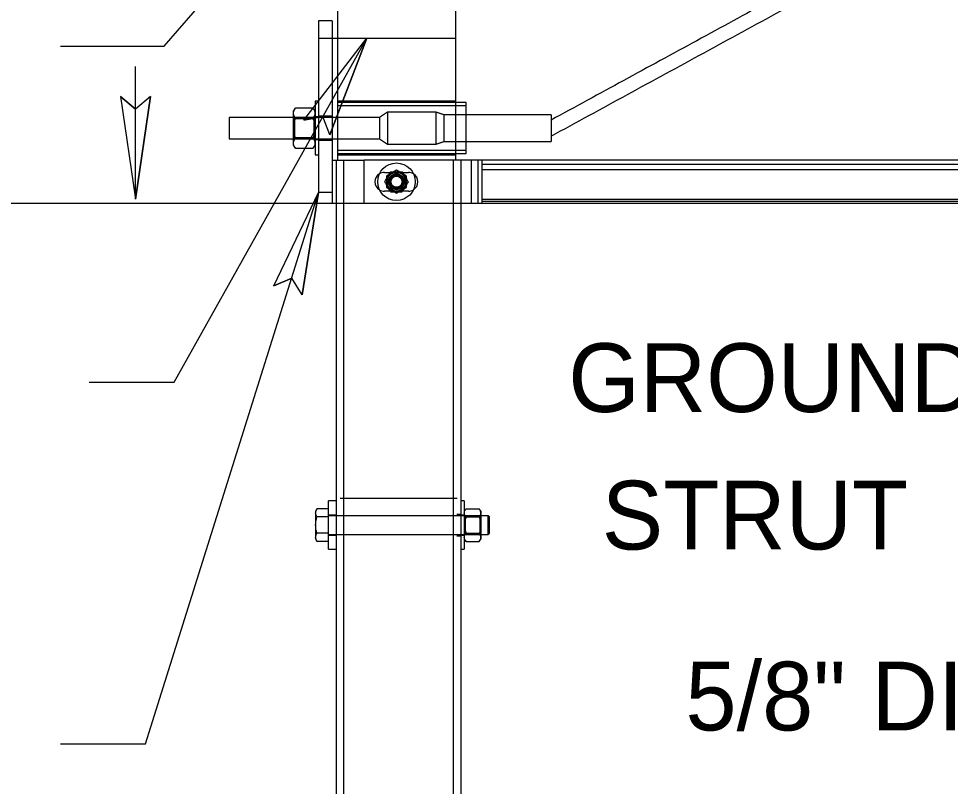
# Model space of a CAD drawing. Extents: x 12.2 to 54.5, y -7.8 to 16.1.
# Drawn here: x 13.367 to 14.18, y 14.128 to 14.798 of the extents above; entities that cross this region are included whole.
import ezdxf

# ---------------------------------------------------------------- set-up
doc = ezdxf.new("R2010")
doc.units = 0
for name, color, linetype in [('BORD-LINE', 7, 'Continuous'), ('DETL-DIMS', 7, 'Continuous'), ('DETL-NOTE', 7, 'Continuous')]:
    doc.layers.add(name, color=color, linetype=linetype)

msp = doc.modelspace()

# ---------------------------------------------------------------- linework, layer by layer
at = {"layer": 'BORD-LINE'}
for p, q in [((13.64499, 15.2566), (13.64499, 14.67435)), ((13.74802, 15.2566), (13.74802, 14.67435)), ((13.6286, 14.7961), (13.6286, 14.64625)), ((13.64031, 14.7961), (13.6286, 14.7961)), ((13.64031, 14.7961), (13.64031, 14.64625)), ((13.6286, 14.7811), (13.74802, 14.7811)), ((13.62561, 14.72586), (13.62561, 14.67903)), ((13.60665, 14.71562), (13.60665, 14.71766)), ((13.60852, 14.72002), (13.62373, 14.72002)), ((13.75738, 14.70244), (13.75738, 14.72469)), ((13.55046, 14.71181), (13.55046, 14.70244)), ((13.60665, 14.70244), (13.60665, 14.71562)), ((13.60667, 14.71181), (13.60667, 14.69308)), ((13.60749, 14.71064), (13.60749, 14.70244)), ((13.60852, 14.71123), (13.62373, 14.71123)), ((13.62479, 14.69425), (13.62479, 14.71064)), ((13.68158, 14.71181), (13.68158, 14.70244)), ((13.6886, 14.71649), (13.6886, 14.70244)), ((13.73777, 14.71415), (13.73777, 14.70244)), ((13.83143, 14.71415), (13.83143, 14.70244)), ((13.55046, 14.70244), (13.55046, 14.69308)), ((13.60665, 14.68926), (13.60665, 14.70244)), ((13.60749, 14.70244), (13.60749, 14.69425)), ((13.68158, 14.70244), (13.68158, 14.69308)), ((13.6886, 14.70244), (13.6886, 14.6884)), ((13.73777, 14.70244), (13.73777, 14.69074)), ((13.75738, 14.6802), (13.75738, 14.70244)), ((13.83143, 14.70244), (13.83143, 14.69074)), ((13.60852, 14.69366), (13.62373, 14.69366)), ((13.60665, 14.68723), (13.60665, 14.68926)), ((13.60852, 14.68487), (13.62373, 14.68487)), ((13.64031, 14.67435), (13.64734, 14.67435)), ((13.64382, 14.67435), (13.64382, 13.32571)), ((13.64734, 14.67435), (13.66841, 14.67435)), ((13.65041, 14.67435), (13.65041, 13.32571)), ((13.66841, 14.63689), (13.66841, 14.67435)), ((13.76206, 14.67435), (13.66841, 14.67435)), ((13.74612, 14.67435), (13.74612, 13.32571)), ((13.7527, 14.67435), (13.7527, 13.32571)), ((13.76206, 14.63689), (13.76206, 14.67435)), ((13.77143, 14.67435), (13.76206, 14.67435)), ((13.76792, 14.63689), (13.76792, 14.67435)), ((13.77143, 14.63689), (13.77143, 14.67435)), ((15.02641, 14.67435), (13.77143, 14.67435)), ((15.02641, 14.6706), (13.77143, 14.6706)), ((13.68597, 14.66381), (13.70704, 14.66381)), ((13.6965, 14.66565), (13.68781, 14.66063)), ((13.68781, 14.66063), (13.68781, 14.6506)), ((13.7052, 14.66063), (13.6965, 14.66565)), ((13.7052, 14.6506), (13.7052, 14.66063)), ((15.02641, 14.66591), (13.77143, 14.66591)), ((13.64031, 14.64625), (13.6286, 14.64625)), ((13.64031, 14.64625), (13.64031, 14.63689)), ((13.70704, 14.64742), (13.68597, 14.64742)), ((13.68781, 14.6506), (13.6965, 14.64558)), ((13.6965, 14.64558), (13.7052, 14.6506)), ((12.39652, 14.63689), (18.94051, 14.63689)), ((15.02641, 14.64026), (13.77143, 14.64026)), ((15.02641, 14.63838), (13.77143, 14.63838)), ((13.63731, 14.33485), (13.63731, 14.37699)), ((13.6473, 14.37939), (13.74936, 14.37942)), ((13.7557, 14.37699), (13.7557, 14.33485)), ((13.626, 14.36821), (13.626, 14.36656)), ((13.63731, 14.37011), (13.6271, 14.37011)), ((13.75733, 14.37011), (13.76859, 14.37011)), ((13.77023, 14.36821), (13.77023, 14.36656)), ((13.626, 14.36656), (13.626, 14.35592)), ((13.63731, 14.36301), (13.6271, 14.36301)), ((13.75571, 14.36411), (13.75571, 14.35592)), ((13.75643, 14.36309), (13.75643, 14.34875)), ((13.75733, 14.36301), (13.76859, 14.36301)), ((13.76951, 14.35592), (13.76951, 14.36309)), ((13.77023, 14.36656), (13.77023, 14.35592)), ((13.77656, 14.34772), (13.77656, 14.36411)), ((13.7778, 14.34896), (13.7778, 14.36287)), ((13.626, 14.35592), (13.626, 14.34528)), ((13.75571, 14.35592), (13.75571, 14.34772)), ((13.76951, 14.34875), (13.76951, 14.35592)), ((13.77023, 14.35592), (13.77023, 14.34528)), ((13.626, 14.34528), (13.626, 14.34363)), ((13.63731, 14.34882), (13.6271, 14.34882)), ((13.75733, 14.34882), (13.76859, 14.34882)), ((13.77023, 14.34528), (13.77023, 14.34363)), ((13.63731, 14.34173), (13.6271, 14.34173)), ((13.75733, 14.34173), (13.76859, 14.34173))]:
    msp.add_line(p, q, dxfattribs=at)
for centre, radius in [((13.69651, 14.65562), 0.01639), ((13.6965, 14.65562), 0.0082), ((13.69651, 14.65562), 0.00702), ((13.6965, 14.65562), 0.00614), ((13.69651, 14.65562), 0.00585), ((13.6965, 14.65562), 0.00498), ((13.69651, 14.65562), 0.00484)]:
    msp.add_circle(centre, radius, dxfattribs=at)
for centre, radius, start, end in [((13.68597, 14.65562), 0.00819, 121.58838, 238.41162), ((13.68597, 14.65561), 0.0082, 90.00567, 121.57898), ((13.69651, 14.65562), 0.00869, 120.00541, 179.99474), ((13.69651, 14.65562), 0.00878, 90.00226, 150.00113), ((13.6965, 14.65562), 0.00869, 59.99841, 120.00159), ((13.69651, 14.65562), 0.00878, 29.99887, 90.00233), ((13.69651, 14.65562), 0.00869, 359.99027, 60.00957), ((13.70704, 14.65562), 0.00819, 58.40904, 90.00139), ((13.70704, 14.65562), 0.00819, 301.57954, 58.42046), ((13.6965, 14.65562), 0.00878, 149.99162, 210.00838), ((13.69651, 14.65562), 0.00869, 180.00526, 239.99459), ((13.69651, 14.65562), 0.00869, 299.99043, 0.00973), ((13.69651, 14.65562), 0.00878, 329.99162, 30.00838), ((13.68597, 14.65562), 0.0082, 238.41635, 269.999), ((13.69651, 14.65562), 0.00878, 209.99887, 269.99774), ((13.6965, 14.65562), 0.00869, 239.99841, 300.00159), ((13.69651, 14.65562), 0.00878, 269.99767, 330.00113), ((13.70704, 14.65561), 0.00819, 269.99609, 301.59348)]:
    msp.add_arc(centre, radius, start, end, dxfattribs=at)
for points, degree in [([(13.83143, 14.69542), (14.36586, 14.98687)], 1), ([(14.3398, 14.98655), (13.83143, 14.70947)], 1), ([(13.6286, 14.72586), (13.62561, 14.72586)], 1), ([(13.74802, 14.72586), (13.64499, 14.72586)], 1), ([(13.60852, 14.72002), (13.60665, 14.71766)], 1), ([(13.60665, 14.71562), (13.60672, 14.7162), (13.60685, 14.71742), (13.60766, 14.71887), (13.60828, 14.7197), (13.60852, 14.72002)], 3), ([(13.62561, 14.71766), (13.62373, 14.72002)], 1), ([(13.62561, 14.71562), (13.62554, 14.7162), (13.62541, 14.71742), (13.6246, 14.71887), (13.62398, 14.7197), (13.62373, 14.72002)], 3), ([(13.74802, 14.72469), (13.64499, 14.72469)], 1), ([(13.75738, 14.7218), (13.64499, 14.7218)], 1), ([(13.75738, 14.72469), (13.74802, 14.72469)], 1), ([(13.60665, 14.71181), (13.55046, 14.71181)], 1), ([(13.60852, 14.71123), (13.60808, 14.71183), (13.60723, 14.71299), (13.60669, 14.71457), (13.60666, 14.71544), (13.60665, 14.71562)], 3), ([(13.64031, 14.71181), (13.60665, 14.71181)], 1), ([(13.60667, 14.71181), (13.60665, 14.71181)], 1), ([(13.60665, 14.70244), (13.60666, 14.70283), (13.60669, 14.7044), (13.60713, 14.70718), (13.60792, 14.70969), (13.60845, 14.71103), (13.60852, 14.71123)], 3), ([(13.60749, 14.71064), (13.60667, 14.71181)], 1), ([(13.62479, 14.71064), (13.60749, 14.71064)], 1), ([(13.62373, 14.71123), (13.62417, 14.71183), (13.62503, 14.71299), (13.62557, 14.71457), (13.6256, 14.71544), (13.62561, 14.71562)], 3), ([(13.62561, 14.70244), (13.6256, 14.70283), (13.62557, 14.7044), (13.62513, 14.70718), (13.62434, 14.70969), (13.62381, 14.71103), (13.62373, 14.71123)], 3), ([(13.62561, 14.71181), (13.62479, 14.71064)], 1), ([(13.6286, 14.71239), (13.62561, 14.71239)], 1), ([(13.64031, 14.71298), (13.6286, 14.71298)], 1), ([(13.64499, 14.71181), (13.64031, 14.71181)], 1), ([(13.68158, 14.71181), (13.64499, 14.71181)], 1), ([(13.6886, 14.71649), (13.68746, 14.71566), (13.68519, 14.71399), (13.68278, 14.71254), (13.68158, 14.71181)], 3), ([(13.73075, 14.71649), (13.6886, 14.71649)], 1), ([(13.73075, 14.71649), (13.73075, 14.7164), (13.73075, 14.71605), (13.73075, 14.71526), (13.73075, 14.71398), (13.73075, 14.71225), (13.73075, 14.71015), (13.73075, 14.70775), (13.73075, 14.70515), (13.73075, 14.70336), (13.73075, 14.70244)], 3), ([(13.73777, 14.71415), (13.73075, 14.71649)], 1), ([(13.75738, 14.71415), (13.73777, 14.71415)], 1), ([(13.83143, 14.71415), (13.75738, 14.71415)], 1), ([(13.83143, 14.70947), (13.83142, 14.70947)], 1), ([(13.60852, 14.69366), (13.60825, 14.6944), (13.60759, 14.69617), (13.60683, 14.6991), (13.60671, 14.70132), (13.60665, 14.70244)], 3), ([(13.62373, 14.69366), (13.62401, 14.6944), (13.62467, 14.69617), (13.62543, 14.6991), (13.62555, 14.70132), (13.62561, 14.70244)], 3), ([(13.73075, 14.70244), (13.73075, 14.70153), (13.73075, 14.69974), (13.73075, 14.69714), (13.73075, 14.69474), (13.73075, 14.69264), (13.73075, 14.69091), (13.73075, 14.68963), (13.73075, 14.68884), (13.73075, 14.68849), (13.73075, 14.6884)], 3), ([(13.55046, 14.69308), (13.60665, 14.69308)], 1), ([(13.60665, 14.68926), (13.60672, 14.68984), (13.60685, 14.69106), (13.60766, 14.69251), (13.60828, 14.69334), (13.60852, 14.69366)], 3), ([(13.60665, 14.69308), (13.64031, 14.69308)], 1), ([(13.60665, 14.69308), (13.60667, 14.69308)], 1), ([(13.60667, 14.69308), (13.60749, 14.69425)], 1), ([(13.60749, 14.69425), (13.62479, 14.69425)], 1), ([(13.62561, 14.68926), (13.62554, 14.68984), (13.62541, 14.69106), (13.6246, 14.69251), (13.62398, 14.69334), (13.62373, 14.69366)], 3), ([(13.62479, 14.69425), (13.62561, 14.69308)], 1), ([(13.64031, 14.69308), (13.64499, 14.69308)], 1), ([(13.64499, 14.69308), (13.68158, 14.69308)], 1), ([(13.68158, 14.69308), (13.68278, 14.69235), (13.68519, 14.6909), (13.68746, 14.68923), (13.6886, 14.6884)], 3), ([(13.60852, 14.68487), (13.60808, 14.68547), (13.60723, 14.68663), (13.60669, 14.68821), (13.60666, 14.68908), (13.60665, 14.68926)], 3), ([(13.60665, 14.68723), (13.60852, 14.68487)], 1), ([(13.62373, 14.68487), (13.62417, 14.68547), (13.62503, 14.68663), (13.62557, 14.68821), (13.6256, 14.68908), (13.62561, 14.68926)], 3), ([(13.62373, 14.68487), (13.62561, 14.68723)], 1), ([(13.62561, 14.6925), (13.6286, 14.6925)], 1), ([(13.6286, 14.69191), (13.64031, 14.69191)], 1), ([(13.6886, 14.6884), (13.73075, 14.6884)], 1), ([(13.73075, 14.6884), (13.73777, 14.69074)], 1), ([(13.73777, 14.69074), (13.75738, 14.69074)], 1), ([(13.75738, 14.69074), (13.83143, 14.69074)], 1), ([(13.62561, 14.67903), (13.6286, 14.67903)], 1), ([(13.64499, 14.68309), (13.75738, 14.68309)], 1), ([(13.64499, 14.6802), (13.74802, 14.6802)], 1), ([(13.64499, 14.67903), (13.74802, 14.67903)], 1), ([(13.74802, 14.6802), (13.75738, 14.6802)], 1), ([(13.6889, 14.66001), (13.68925, 14.66062), (13.68996, 14.66184), (13.6908, 14.66331), (13.69129, 14.66416), (13.69143, 14.6644)], 3), ([(13.69143, 14.6644), (13.69187, 14.6644), (13.69291, 14.6644), (13.6946, 14.6644), (13.69586, 14.6644), (13.6965, 14.6644)], 3), ([(13.6965, 14.6644), (13.69662, 14.6644), (13.69738, 14.6644), (13.69877, 14.6644), (13.70034, 14.6644), (13.70128, 14.6644), (13.70158, 14.6644)], 3), ([(13.70158, 14.6644), (13.70198, 14.66371), (13.70281, 14.66227), (13.70366, 14.6608), (13.7041, 14.66003), (13.70411, 14.66001)], 3), ([(13.68636, 14.65562), (13.68676, 14.65631), (13.6876, 14.65775), (13.68843, 14.65922), (13.68889, 14.65999), (13.6889, 14.66001)], 3), ([(13.6889, 14.65122), (13.68854, 14.65184), (13.68784, 14.65306), (13.68699, 14.65452), (13.6865, 14.65538), (13.68636, 14.65562)], 3), ([(13.70411, 14.66001), (13.70447, 14.6594), (13.70517, 14.65817), (13.70602, 14.65671), (13.70651, 14.65586), (13.70665, 14.65562)], 3), ([(13.70665, 14.65562), (13.70625, 14.65492), (13.70542, 14.65348), (13.70457, 14.65202), (13.70412, 14.65124), (13.70411, 14.65122)], 3), ([(13.69143, 14.64683), (13.69103, 14.64752), (13.6902, 14.64897), (13.68935, 14.65043), (13.68891, 14.6512), (13.6889, 14.65122)], 3), ([(13.69143, 14.64683), (13.69187, 14.64683), (13.69291, 14.64683), (13.6946, 14.64683), (13.69586, 14.64683), (13.6965, 14.64683)], 3), ([(13.6965, 14.64683), (13.69662, 14.64683), (13.69738, 14.64683), (13.69877, 14.64683), (13.70034, 14.64683), (13.70128, 14.64683), (13.70158, 14.64683)], 3), ([(13.70411, 14.65122), (13.70376, 14.65061), (13.70305, 14.64939), (13.70221, 14.64793), (13.70172, 14.64707), (13.70158, 14.64683)], 3), ([(13.64378, 14.37699), (13.63731, 14.37699)], 1), ([(13.7557, 14.37699), (13.7527, 14.37699)], 1), ([(13.626, 14.36656), (13.626, 14.36664), (13.62601, 14.36729), (13.62627, 14.36854), (13.62682, 14.36957), (13.6271, 14.37011)], 3), ([(13.6271, 14.37011), (13.626, 14.36821)], 1), ([(13.7557, 14.36656), (13.75576, 14.36706), (13.75591, 14.36814), (13.75665, 14.36928), (13.75717, 14.36991), (13.75733, 14.37011)], 3), ([(13.75733, 14.37011), (13.7557, 14.36821)], 1), ([(13.77023, 14.36656), (13.77016, 14.36706), (13.77002, 14.36814), (13.76927, 14.36928), (13.76875, 14.36991), (13.76859, 14.37011)], 3), ([(13.77023, 14.36821), (13.76859, 14.37011)], 1), ([(13.6271, 14.36301), (13.62679, 14.36358), (13.62619, 14.36469), (13.62606, 14.36595), (13.626, 14.36656)], 3), ([(13.626, 14.35592), (13.62604, 14.35685), (13.62611, 14.35874), (13.62657, 14.3611), (13.62696, 14.36251), (13.6271, 14.36301)], 3), ([(13.64383, 14.3647), (13.63731, 14.3647)], 1), ([(13.77656, 14.36411), (13.63731, 14.36411)], 1), ([(13.7527, 14.36528), (13.74919, 14.36528)], 1), ([(13.7557, 14.3647), (13.7527, 14.3647)], 1), ([(13.75733, 14.36301), (13.75691, 14.36355), (13.75609, 14.36457), (13.7557, 14.3659), (13.7557, 14.36654), (13.7557, 14.36656)], 3), ([(13.75571, 14.36411), (13.7557, 14.36411)], 1), ([(13.75733, 14.36301), (13.75709, 14.36241), (13.75651, 14.36099), (13.75585, 14.35862), (13.75575, 14.35683), (13.7557, 14.35592)], 3), ([(13.75643, 14.36309), (13.75571, 14.36411)], 1), ([(13.76951, 14.36309), (13.75643, 14.36309)], 1), ([(13.76859, 14.36301), (13.76902, 14.36355), (13.76983, 14.36457), (13.77023, 14.3659), (13.77023, 14.36654), (13.77023, 14.36656)], 3), ([(13.76859, 14.36301), (13.76884, 14.36241), (13.76941, 14.36099), (13.77008, 14.35862), (13.77018, 14.35683), (13.77023, 14.35592)], 3), ([(13.77023, 14.36411), (13.76951, 14.36309)], 1), ([(13.7778, 14.36287), (13.77656, 14.36411)], 1), ([(13.6271, 14.34882), (13.62686, 14.34971), (13.6264, 14.35148), (13.62605, 14.35387), (13.62602, 14.35535), (13.626, 14.35592)], 3), ([(13.7557, 14.35592), (13.7557, 14.35576), (13.75571, 14.35469), (13.75598, 14.35271), (13.75663, 14.35052), (13.75716, 14.34924), (13.75733, 14.34882)], 3), ([(13.77023, 14.35592), (13.77023, 14.35576), (13.77022, 14.35469), (13.76995, 14.35271), (13.76929, 14.35052), (13.76877, 14.34924), (13.76859, 14.34882)], 3), ([(13.626, 14.34528), (13.626, 14.34536), (13.62601, 14.34601), (13.62627, 14.34725), (13.62682, 14.34829), (13.6271, 14.34882)], 3), ([(13.6271, 14.34173), (13.62679, 14.3423), (13.62619, 14.34341), (13.62606, 14.34466), (13.626, 14.34528)], 3), ([(13.626, 14.34363), (13.6271, 14.34173)], 1), ([(13.63731, 14.34772), (13.77656, 14.34772)], 1), ([(13.63731, 14.34713), (13.64373, 14.34713)], 1), ([(13.74919, 14.34655), (13.7527, 14.34655)], 1), ([(13.7527, 14.34713), (13.7557, 14.34713)], 1), ([(13.7557, 14.34528), (13.75576, 14.34578), (13.75591, 14.34686), (13.75665, 14.348), (13.75717, 14.34863), (13.75733, 14.34882)], 3), ([(13.7557, 14.34772), (13.75571, 14.34772)], 1), ([(13.75733, 14.34173), (13.75691, 14.34226), (13.75609, 14.34329), (13.7557, 14.34462), (13.7557, 14.34526), (13.7557, 14.34528)], 3), ([(13.7557, 14.34528), (13.75574, 14.34506)], 1), ([(13.7557, 14.34363), (13.75733, 14.34173)], 1), ([(13.75571, 14.34772), (13.75643, 14.34875)], 1), ([(13.75643, 14.34875), (13.76951, 14.34875)], 1), ([(13.77023, 14.34528), (13.77016, 14.34578), (13.77002, 14.34686), (13.76927, 14.348), (13.76875, 14.34863), (13.76859, 14.34882)], 3), ([(13.76859, 14.34173), (13.76902, 14.34226), (13.76983, 14.34329), (13.77023, 14.34462), (13.77023, 14.34526), (13.77023, 14.34528)], 3), ([(13.76859, 14.34173), (13.77023, 14.34363)], 1), ([(13.76951, 14.34875), (13.77023, 14.34772)], 1), ([(13.77656, 14.34772), (13.7778, 14.34896)], 1), ([(13.63731, 14.33485), (13.64373, 14.33485)], 1), ([(13.7527, 14.33485), (13.7557, 14.33485)], 1)]:
    msp.add_open_spline(points, degree=degree, dxfattribs=at)
at = {"layer": 'DETL-DIMS'}
for p, q in [((13.49393, 14.77401), (13.64499, 14.9492)), ((13.40331, 14.77401), (13.49393, 14.77401)), ((13.50249, 14.48077), (13.67075, 14.7811)), ((13.6157, 14.70924), (13.67075, 14.7811)), ((13.63847, 14.69648), (13.67075, 14.7811)), ((13.4687, 14.64044), (13.4687, 14.75637)), ((13.4558, 14.73004), (13.4687, 14.64044)), ((13.4558, 14.73004), (13.4687, 14.71894)), ((13.4819, 14.73004), (13.4687, 14.64044)), ((13.4819, 14.73004), (13.4687, 14.71894)), ((13.6157, 14.70924), (13.63238, 14.71262)), ((13.63847, 14.69648), (13.63238, 14.71262)), ((13.47754, 14.16513), (13.6286, 14.64625)), ((13.58946, 14.56463), (13.6286, 14.64625)), ((13.61436, 14.55681), (13.6286, 14.64625)), ((13.58946, 14.56463), (13.60509, 14.57136)), ((13.61436, 14.55681), (13.60509, 14.57136)), ((13.42827, 14.48077), (13.50249, 14.48077)), ((13.40332, 14.16513), (13.47754, 14.16513))]:
    msp.add_line(p, q, dxfattribs=at)
for points in [[(13.6157, 14.70924), (13.67075, 14.7811), (13.63847, 14.69648), (13.63238, 14.71262)], [(13.4558, 14.73004), (13.4687, 14.64044), (13.4819, 14.73004), (13.4687, 14.71894)], [(13.58946, 14.56463), (13.6286, 14.64625), (13.61436, 14.55681), (13.60509, 14.57136)]]:
    msp.add_lwpolyline(points, close=True, dxfattribs=at)

# ---------------------------------------------------------------- texts
at = {"layer": 'DETL-NOTE'}
for s, p in [('GROUND', (13.84646, 14.45463)), ('STRUT', (13.87571, 14.33463)), ('5/8" DIA. X 1O"', (13.9487, 14.17669))]:
    msp.add_text(s, height=0.06, dxfattribs=at).set_placement(p)

doc.saveas('drawing.dxf')
